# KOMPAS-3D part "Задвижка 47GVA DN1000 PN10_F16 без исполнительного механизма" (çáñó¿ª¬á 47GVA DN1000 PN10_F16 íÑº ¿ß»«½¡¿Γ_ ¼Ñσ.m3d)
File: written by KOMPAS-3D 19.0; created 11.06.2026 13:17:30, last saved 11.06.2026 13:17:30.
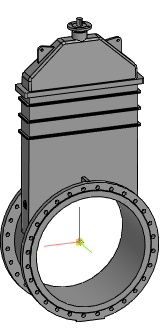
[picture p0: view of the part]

Document properties: Автор: Евгений; Полное имя файла: Z:\3.Личные\kachalov\001_3d для проектировщиков\2.2 Тип 47GVA, 47GVA.Z\_stp\_stp_Задвижка 47GVA DN40-DN1000 без исп.мех\Задвижка 47GVA DN1000 PN10_F16 без исполнит_ мех.m3d

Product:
- Part/product: Задвижка 47GVA DN1000 PN10_F16 без исполнительного механизма

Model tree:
1. Операция без истории:1  (labels: Задвижка 47GVA DN1000 PN10_F16 без исполнительного механизма)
